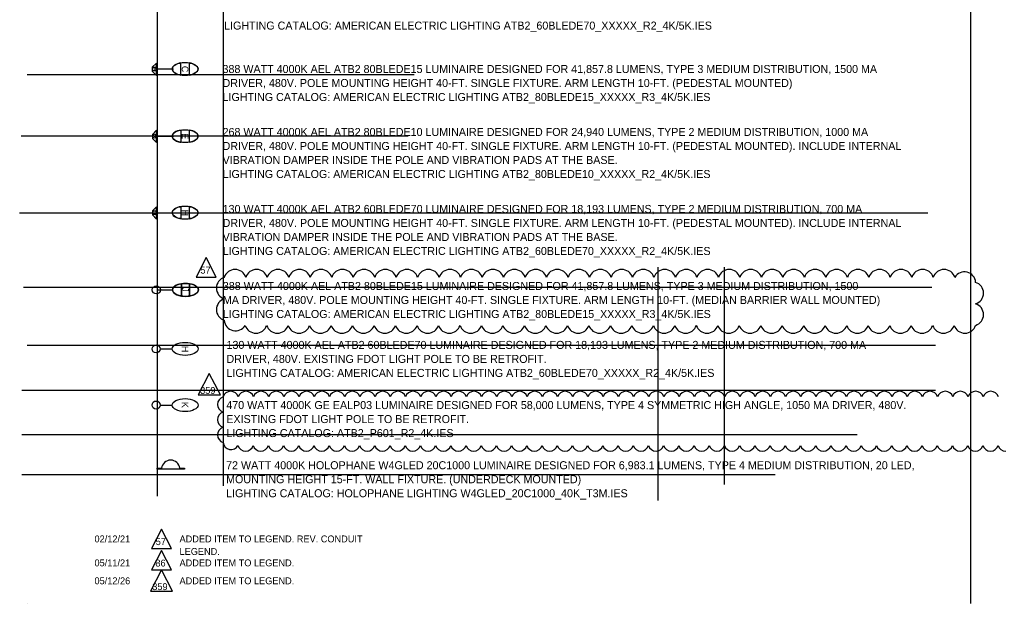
# Model space of a CAD drawing. Extents: x -0.7 to 15.2, y -0.9 to 9.6.
# Drawn here: x -0.62 to 7.94, y -0.9 to 4.21 of the extents above; entities that cross this region are included whole.
import ezdxf

# ---------------------------------------------------------------- set-up
doc = ezdxf.new("R2010")
doc.units = 0
for name, color, linetype in [('ActivePointCell_dp', 7, 'Continuous'), ('AdhocPoint_dp', 7, 'Continuous'), ('Cloud_dp', 7, 'Continuous'), ('LightingMisc', 7, 'Continuous'), ('Miscellaneous2', 7, 'Continuous'), ('PoleLight', 7, 'Continuous'), ('TextLabel', 7, 'Continuous'), ('TextMisc', 7, 'Continuous')]:
    doc.layers.add(name, color=color, linetype=linetype)

msp = doc.modelspace()

# ---------------------------------------------------------------- linework, layer by layer
at = {"layer": 'ActivePointCell_dp'}
for p, q in [((7.7, -0.9), (7.7, 9.6)), ((0.5844, 9.2534), (0.5844, 0.0367)), ((1.1641, 0.1282), (1.1641, 9.1337)), ((2.8316, 3.722), (-0.5519, 3.722)), ((2.7789, 3.1858), (-0.6046, 3.1858)), ((7.3238, 2.5135), (-0.6178, 2.5135)), ((4.9633, 2.0414), (4.9633, 0)), ((5.5423, 2.0414), (5.5423, 0.1403)), ((7.3568, 1.862), (-0.5847, 1.862)), ((7.39, 1.3545), (-0.5516, 1.3545)), ((7.39, 0.9614), (-0.599, 0.9614)), ((6.7052, 0.5747), (-0.599, 0.5747)), ((5.9878, 0.2247), (-0.599, 0.2247))]:
    msp.add_line(p, q, dxfattribs=at)
at = {"layer": 'AdhocPoint_dp'}
msp.add_line((-0.55, -0.9), (-0.55, -0.9), dxfattribs=at)
at = {"layer": 'Cloud_dp'}
for points in [[(1.0137, 2.1234), (0.9257, 1.9538), (1.1017, 1.9538)], [(1.0412, 1.1101), (0.9444, 0.9236), (1.138, 0.9236)], [(0.6228, -0.2504), (0.5348, -0.42), (0.7109, -0.42)], [(0.6228, -0.4378), (0.5348, -0.6074), (0.7109, -0.6074)], [(0.6228, -0.6056), (0.526, -0.7921), (0.7197, -0.7921)]]:
    msp.add_lwpolyline(points, close=True, dxfattribs=at)
for centre, radius, start, end in [((1.266, 1.9216), 0.0985, 17.5, 162.5), ((1.4538, 1.9216), 0.0985, 17.5, 162.5), ((1.6417, 1.9216), 0.0985, 17.5, 162.5), ((1.8295, 1.9216), 0.0985, 17.5, 162.5), ((2.0173, 1.9216), 0.0985, 17.5, 162.5), ((2.2051, 1.9216), 0.0985, 17.5, 162.5), ((2.393, 1.9216), 0.0985, 17.5, 162.5), ((2.5808, 1.9216), 0.0985, 17.5, 162.5), ((2.7686, 1.9216), 0.0985, 17.5, 162.5), ((2.9565, 1.9216), 0.0985, 17.5, 162.5), ((3.1443, 1.9216), 0.0985, 17.5, 162.5), ((3.3321, 1.9216), 0.0985, 17.5, 162.5), ((3.5199, 1.9216), 0.0985, 17.5, 162.5), ((3.7078, 1.9216), 0.0985, 17.5, 162.5), ((3.8956, 1.9216), 0.0985, 17.5, 162.5), ((4.0834, 1.9216), 0.0985, 17.5, 162.5), ((4.2713, 1.9216), 0.0985, 17.5, 162.5), ((4.4591, 1.9216), 0.0985, 17.5, 162.5), ((4.6469, 1.9216), 0.0985, 17.5, 162.5), ((4.8347, 1.9216), 0.0985, 17.5, 162.5), ((5.0226, 1.9216), 0.0985, 17.5, 162.5), ((5.2104, 1.9216), 0.0985, 17.5, 162.5), ((5.3982, 1.9216), 0.0985, 17.5, 162.5), ((5.5861, 1.9216), 0.0985, 17.5, 162.5), ((5.7739, 1.9216), 0.0985, 17.5, 162.5), ((5.9617, 1.9216), 0.0985, 17.5, 162.5), ((6.1495, 1.9216), 0.0985, 17.5, 162.5), ((6.3374, 1.9216), 0.0985, 17.5, 162.5), ((6.5252, 1.9216), 0.0985, 17.5, 162.5), ((6.713, 1.9216), 0.0985, 17.5, 162.5), ((6.9009, 1.9216), 0.0985, 17.5, 162.5), ((7.0887, 1.9216), 0.0985, 17.5, 162.5), ((7.2765, 1.9216), 0.0985, 17.5, 162.5), ((7.4643, 1.9216), 0.0985, 17.5, 162.5), ((7.6425, 1.9004), 0.0984, 3.94339, 148.94339), ((1.2017, 1.8573), 0.0985, 107.5, 252.5), ((7.7111, 1.8133), 0.0985, 287.5, 72.5), ((1.2017, 1.6695), 0.0985, 107.5, 252.5), ((7.7111, 1.6255), 0.0985, 287.5, 72.5), ((1.2702, 1.5823), 0.0984, 183.94339, 328.94339), ((1.4484, 1.5612), 0.0985, 197.5, 342.5), ((1.6363, 1.5612), 0.0985, 197.5, 342.5), ((1.8241, 1.5612), 0.0985, 197.5, 342.5), ((2.0119, 1.5612), 0.0985, 197.5, 342.5), ((2.1997, 1.5612), 0.0985, 197.5, 342.5), ((2.3876, 1.5612), 0.0985, 197.5, 342.5), ((2.5754, 1.5612), 0.0985, 197.5, 342.5), ((2.7632, 1.5612), 0.0985, 197.5, 342.5), ((2.9511, 1.5612), 0.0985, 197.5, 342.5), ((3.1389, 1.5612), 0.0985, 197.5, 342.5), ((3.3267, 1.5612), 0.0985, 197.5, 342.5), ((3.5145, 1.5612), 0.0985, 197.5, 342.5), ((3.7024, 1.5612), 0.0985, 197.5, 342.5), ((3.8902, 1.5612), 0.0985, 197.5, 342.5), ((4.078, 1.5612), 0.0985, 197.5, 342.5), ((4.2659, 1.5612), 0.0985, 197.5, 342.5), ((4.4537, 1.5612), 0.0985, 197.5, 342.5), ((4.6415, 1.5612), 0.0985, 197.5, 342.5), ((4.8293, 1.5612), 0.0985, 197.5, 342.5), ((5.0172, 1.5612), 0.0985, 197.5, 342.5), ((5.205, 1.5612), 0.0985, 197.5, 342.5), ((5.3928, 1.5612), 0.0985, 197.5, 342.5), ((5.5807, 1.5612), 0.0985, 197.5, 342.5), ((5.7685, 1.5612), 0.0985, 197.5, 342.5), ((5.9563, 1.5612), 0.0985, 197.5, 342.5), ((6.1441, 1.5612), 0.0985, 197.5, 342.5), ((6.332, 1.5612), 0.0985, 197.5, 342.5), ((6.5198, 1.5612), 0.0985, 197.5, 342.5), ((6.7076, 1.5612), 0.0985, 197.5, 342.5), ((6.8955, 1.5612), 0.0985, 197.5, 342.5), ((7.0833, 1.5612), 0.0985, 197.5, 342.5), ((7.2711, 1.5612), 0.0985, 197.5, 342.5), ((7.4589, 1.5612), 0.0985, 197.5, 342.5), ((7.6468, 1.5612), 0.0985, 197.5, 342.5), ((1.228, 0.885), 0.0697, 17.5, 162.5), ((1.3609, 0.885), 0.0697, 17.5, 162.5), ((1.4939, 0.885), 0.0697, 17.5, 162.5), ((1.6268, 0.885), 0.0697, 17.5, 162.5), ((1.7597, 0.885), 0.0697, 17.5, 162.5), ((1.8926, 0.885), 0.0697, 17.5, 162.5), ((2.0255, 0.885), 0.0697, 17.5, 162.5), ((2.1584, 0.885), 0.0697, 17.5, 162.5), ((2.2913, 0.885), 0.0697, 17.5, 162.5), ((2.4242, 0.885), 0.0697, 17.5, 162.5), ((2.5571, 0.885), 0.0697, 17.5, 162.5), ((2.69, 0.885), 0.0697, 17.5, 162.5), ((2.8229, 0.885), 0.0697, 17.5, 162.5), ((2.9559, 0.885), 0.0697, 17.5, 162.5), ((3.0888, 0.885), 0.0697, 17.5, 162.5), ((3.2217, 0.885), 0.0697, 17.5, 162.5), ((3.3546, 0.885), 0.0697, 17.5, 162.5), ((3.4875, 0.885), 0.0697, 17.5, 162.5), ((3.6204, 0.885), 0.0697, 17.5, 162.5), ((3.7533, 0.885), 0.0697, 17.5, 162.5), ((3.8862, 0.885), 0.0697, 17.5, 162.5), ((4.0191, 0.885), 0.0697, 17.5, 162.5), ((4.152, 0.885), 0.0697, 17.5, 162.5), ((4.2849, 0.885), 0.0697, 17.5, 162.5), ((4.4178, 0.885), 0.0697, 17.5, 162.5), ((4.5508, 0.885), 0.0697, 17.5, 162.5), ((4.6837, 0.885), 0.0697, 17.5, 162.5), ((4.8166, 0.885), 0.0697, 17.5, 162.5), ((4.9495, 0.885), 0.0697, 17.5, 162.5), ((5.0824, 0.885), 0.0697, 17.5, 162.5), ((5.2153, 0.885), 0.0697, 17.5, 162.5), ((5.3482, 0.885), 0.0697, 17.5, 162.5), ((5.4811, 0.885), 0.0697, 17.5, 162.5), ((5.614, 0.885), 0.0697, 17.5, 162.5), ((5.7469, 0.885), 0.0697, 17.5, 162.5), ((5.8798, 0.885), 0.0697, 17.5, 162.5), ((6.0128, 0.885), 0.0697, 17.5, 162.5), ((6.1457, 0.885), 0.0697, 17.5, 162.5), ((6.2786, 0.885), 0.0697, 17.5, 162.5), ((6.4115, 0.885), 0.0697, 17.5, 162.5), ((6.5444, 0.885), 0.0697, 17.5, 162.5), ((6.6773, 0.885), 0.0697, 17.5, 162.5), ((6.8102, 0.885), 0.0697, 17.5, 162.5), ((6.9431, 0.885), 0.0697, 17.5, 162.5), ((7.076, 0.885), 0.0697, 17.5, 162.5), ((7.2089, 0.885), 0.0697, 17.5, 162.5), ((7.3418, 0.885), 0.0697, 17.5, 162.5), ((7.4748, 0.885), 0.0697, 17.5, 162.5), ((7.6077, 0.885), 0.0697, 17.5, 162.5), ((7.7406, 0.885), 0.0697, 17.5, 162.5), ((7.8735, 0.885), 0.0697, 17.5, 162.5), ((1.1825, 0.8395), 0.0697, 107.5, 252.5), ((1.1825, 0.7066), 0.0697, 107.5, 252.5), ((1.1825, 0.5737), 0.0697, 107.5, 252.5), ((1.2308, 0.5145), 0.0696, 185.94047, 330.94047), ((1.3582, 0.5016), 0.0697, 197.5, 342.5), ((1.4911, 0.5016), 0.0697, 197.5, 342.5), ((1.624, 0.5016), 0.0697, 197.5, 342.5), ((1.7569, 0.5016), 0.0697, 197.5, 342.5), ((1.8898, 0.5016), 0.0697, 197.5, 342.5), ((2.0227, 0.5016), 0.0697, 197.5, 342.5), ((2.1556, 0.5016), 0.0697, 197.5, 342.5), ((2.2885, 0.5016), 0.0697, 197.5, 342.5), ((2.4214, 0.5016), 0.0697, 197.5, 342.5), ((2.5543, 0.5016), 0.0697, 197.5, 342.5), ((2.6873, 0.5016), 0.0697, 197.5, 342.5), ((2.8202, 0.5016), 0.0697, 197.5, 342.5), ((2.9531, 0.5016), 0.0697, 197.5, 342.5), ((3.086, 0.5016), 0.0697, 197.5, 342.5), ((3.2189, 0.5016), 0.0697, 197.5, 342.5), ((3.3518, 0.5016), 0.0697, 197.5, 342.5), ((3.4847, 0.5016), 0.0697, 197.5, 342.5), ((3.6176, 0.5016), 0.0697, 197.5, 342.5), ((3.7505, 0.5016), 0.0697, 197.5, 342.5), ((3.8834, 0.5016), 0.0697, 197.5, 342.5), ((4.0163, 0.5016), 0.0697, 197.5, 342.5), ((4.1493, 0.5016), 0.0697, 197.5, 342.5), ((4.2822, 0.5016), 0.0697, 197.5, 342.5), ((4.4151, 0.5016), 0.0697, 197.5, 342.5), ((4.548, 0.5016), 0.0697, 197.5, 342.5), ((4.6809, 0.5016), 0.0697, 197.5, 342.5), ((4.8138, 0.5016), 0.0697, 197.5, 342.5), ((4.9467, 0.5016), 0.0697, 197.5, 342.5), ((5.0796, 0.5016), 0.0697, 197.5, 342.5), ((5.2125, 0.5016), 0.0697, 197.5, 342.5), ((5.3454, 0.5016), 0.0697, 197.5, 342.5), ((5.4783, 0.5016), 0.0697, 197.5, 342.5), ((5.6112, 0.5016), 0.0697, 197.5, 342.5), ((5.7442, 0.5016), 0.0697, 197.5, 342.5), ((5.8771, 0.5016), 0.0697, 197.5, 342.5), ((6.01, 0.5016), 0.0697, 197.5, 342.5), ((6.1429, 0.5016), 0.0697, 197.5, 342.5), ((6.2758, 0.5016), 0.0697, 197.5, 342.5), ((6.4087, 0.5016), 0.0697, 197.5, 342.5), ((6.5416, 0.5016), 0.0697, 197.5, 342.5), ((6.6745, 0.5016), 0.0697, 197.5, 342.5), ((6.8074, 0.5016), 0.0697, 197.5, 342.5), ((6.9403, 0.5016), 0.0697, 197.5, 342.5), ((7.0732, 0.5016), 0.0697, 197.5, 342.5), ((7.2062, 0.5016), 0.0697, 197.5, 342.5), ((7.3391, 0.5016), 0.0697, 197.5, 342.5), ((7.472, 0.5016), 0.0697, 197.5, 342.5), ((7.6049, 0.5016), 0.0697, 197.5, 342.5), ((7.7378, 0.5016), 0.0697, 197.5, 342.5), ((7.8707, 0.5016), 0.0697, 197.5, 342.5), ((8.0036, 0.5016), 0.0697, 197.5, 342.5)]:
    msp.add_arc(centre, radius, start, end, dxfattribs=at)
at = {"layer": 'LightingMisc'}
for p, q in [((0.584, 0.2734), (0.5839, 0.2814)), ((0.5839, 0.2814), (0.6241, 0.2814)), ((0.8228, 0.2739), (0.584, 0.2734)), ((0.7826, 0.2818), (0.8228, 0.2819)), ((0.8228, 0.2819), (0.8228, 0.2739))]:
    msp.add_line(p, q, dxfattribs=at)
msp.add_arc((0.7034, 0.2737), 0.0796, 5.86956, 174.39115, dxfattribs=at)
at = {"layer": 'Miscellaneous2'}
msp.add_ellipse((0.8323, 1.8418), major_axis=(-0.1133, 0), ratio=0.5, start_param=4.391241, end_param=4.391271, dxfattribs=at)
at = {"layer": 'PoleLight'}
for p, q in [((0.5583, 3.7731), (0.7274, 3.7731)), ((0.7932, 3.7193), (0.7932, 3.8268)), ((0.8647, 3.8268), (0.8647, 3.7193)), ((0.5587, 3.1858), (0.7277, 3.1858)), ((0.7936, 3.132), (0.7936, 3.2395)), ((0.8651, 3.2395), (0.8651, 3.132)), ((0.7936, 2.463), (0.7936, 2.5705)), ((0.8651, 2.5705), (0.8651, 2.463)), ((0.5587, 2.5167), (0.7277, 2.5167)), ((0.7965, 1.7881), (0.7965, 1.8956)), ((0.7965, 1.8944), (0.7965, 1.7881)), ((0.868, 1.8956), (0.868, 1.7881)), ((0.868, 1.7881), (0.868, 1.8956)), ((0.5929, 1.8415), (0.7238, 1.8415)), ((0.6113, 1.3255), (0.7161, 1.3255)), ((0.6113, 0.8345), (0.7161, 0.8345))]:
    msp.add_line(p, q, dxfattribs=at)
for points in [[(0.5425, 3.789), (0.5426, 3.7532), (0.5783, 3.7175), (0.5782, 3.8248)], [(0.5429, 3.2017), (0.543, 3.1659), (0.5786, 3.1302), (0.5786, 3.2374)], [(0.5429, 2.5327), (0.543, 2.4969), (0.5786, 2.4612), (0.5786, 2.5684)]]:
    msp.add_lwpolyline(points, close=True, dxfattribs=at)
for centre, radius in [((0.5617, 3.7728), 0.0163), ((0.562, 3.1855), 0.0163), ((0.562, 2.5165), 0.0163), ((0.5779, 1.8415), 0.0354), ((0.5779, 1.8415), 0.0354), ((0.576, 1.3255), 0.0354), ((0.576, 0.8345), 0.0354)]:
    msp.add_circle(centre, radius, dxfattribs=at)
for centre in [(0.8289, 3.7731), (0.8293, 3.1858), (0.8293, 2.5167), (0.8323, 1.8418), (0.8293, 1.3255), (0.8293, 0.8345)]:
    msp.add_ellipse(centre, major_axis=(-0.1133, 0), ratio=0.5, dxfattribs=at)
for centre, start_param, end_param in [((0.8289, 3.7731), 5.033538, 6.283185), ((0.8289, 3.7731), 0, 0.847605), ((0.8289, 3.7731), 1.891945, 4.391241), ((0.8289, 3.7731), 0.847605, 1.249648), ((0.8293, 3.1858), 5.033538, 6.283185), ((0.8293, 3.1858), 0, 0.847605), ((0.8293, 3.1858), 1.891945, 4.391241), ((0.8293, 3.1858), 0.847605, 1.249648), ((0.8293, 2.5167), 5.033538, 6.283185), ((0.8293, 2.5167), 1.891945, 4.391241), ((0.8293, 2.5167), 0, 0.847605), ((0.8293, 2.5167), 0.847605, 1.249648), ((0.8323, 1.8418), 5.033538, 6.283185), ((0.8323, 1.8418), 4.391271, 5.033538), ((0.8323, 1.8418), 1.891945, 4.391241), ((0.8323, 1.8418), 0, 0.847605), ((0.8323, 1.8418), 0.847605, 1.249648), ((0.8323, 1.8418), 1.249648, 1.891946)]:
    msp.add_ellipse(centre, major_axis=(-0.1133, 0), ratio=0.5, start_param=start_param, end_param=end_param, dxfattribs=at)

# ---------------------------------------------------------------- texts
at = {"layer": 'Cloud_dp'}
for s, p in [('57', (0.963, 1.984)), ('359', (0.9607, 0.9323)), ('02/12/21', (0.0373, -0.3659)), ('57', (0.5721, -0.3898)), ('ADDED ITEM TO LEGEND. REV. CONDUIT ', (0.7806, -0.3659)), ('LEGEND.', (0.7806, -0.4759)), ('05/11/21', (0.0373, -0.5754)), ('86', (0.5695, -0.5772)), ('ADDED ITEM TO LEGEND.', (0.7806, -0.5754)), ('05/12/26', (0.0373, -0.7324)), ('ADDED ITEM TO LEGEND.', (0.7806, -0.7324)), ('359', (0.5423, -0.7834))]:
    msp.add_text(s, height=0.06, dxfattribs=at).set_placement(p)
at = {"layer": 'TextLabel'}
for s, rotation, p in [('C', 270.00003, (0.8003, 3.7999)), ('E', 270.00003, (0.8007, 3.2115)), ('H', 270.00003, (0.8007, 2.5429)), ('J', 270.00005, (0.8037, 1.8634)), ('H', 270.00003, (0.8007, 1.3517)), ('K', 270.00003, (0.8007, 0.8616))]:
    msp.add_text(s, height=0.0572, rotation=rotation, dxfattribs=at).set_placement(p)
at = {"layer": 'TextMisc'}
for s, p in [('LIGHTING CATALOG: AMERICAN ELECTRIC LIGHTING ATB2_60BLEDE70_XXXXX_R2_4K/5K.IES', (1.1699, 4.1176)), ('388 WATT 4000K AEL ATB2 80BLEDE15 LUMINAIRE DESIGNED FOR 41,857.8 LUMENS, TYPE 3 MEDIUM DISTRIBUTION, 1500 MA ', (1.1566, 3.7381)), ('DRIVER, 480V. POLE MOUNTING HEIGHT 40-FT. SINGLE FIXTURE. ARM LENGTH 10-FT. (PEDESTAL MOUNTED)', (1.1566, 3.6156)), ('LIGHTING CATALOG: AMERICAN ELECTRIC LIGHTING ATB2_80BLEDE15_XXXXX_R3_4K/5K.IES', (1.1566, 3.4931)), ('268 WATT 4000K AEL ATB2 80BLEDE10 LUMINAIRE DESIGNED FOR 24,940 LUMENS, TYPE 2 MEDIUM DISTRIBUTION, 1000 MA ', (1.157, 3.1875)), ('DRIVER, 480V. POLE MOUNTING HEIGHT 40-FT. SINGLE FIXTURE. ARM LENGTH 10-FT. (PEDESTAL MOUNTED). INCLUDE INTERNAL ', (1.157, 3.065)), ('VIBRATION DAMPER INSIDE THE POLE AND VIBRATION PADS AT THE BASE.', (1.157, 2.9425)), ('LIGHTING CATALOG: AMERICAN ELECTRIC LIGHTING ATB2_80BLEDE10_XXXXX_R2_4K/5K.IES', (1.157, 2.82)), ('130 WATT 4000K AEL ATB2 60BLEDE70 LUMINAIRE DESIGNED FOR 18,193 LUMENS, TYPE 2 MEDIUM DISTRIBUTION, 700 MA ', (1.1574, 2.5143)), ('DRIVER, 480V. POLE MOUNTING HEIGHT 40-FT. SINGLE FIXTURE. ARM LENGTH 10-FT. (PEDESTAL MOUNTED). INCLUDE INTERNAL ', (1.1574, 2.3918)), ('VIBRATION DAMPER INSIDE THE POLE AND VIBRATION PADS AT THE BASE.', (1.1574, 2.2693)), ('LIGHTING CATALOG: AMERICAN ELECTRIC LIGHTING ATB2_60BLEDE70_XXXXX_R2_4K/5K.IES', (1.1574, 2.1468)), ('388 WATT 4000K AEL ATB2 80BLEDE15 LUMINAIRE DESIGNED FOR 41,857.8 LUMENS, TYPE 3 MEDIUM DISTRIBUTION, 1500 ', (1.1594, 1.8408)), ('MA DRIVER, 480V. POLE MOUNTING HEIGHT 40-FT. SINGLE FIXTURE. ARM LENGTH 10-FT. (MEDIAN BARRIER WALL MOUNTED)', (1.1594, 1.7183)), ('LIGHTING CATALOG: AMERICAN ELECTRIC LIGHTING ATB2_80BLEDE15_XXXXX_R3_4K/5K.IES', (1.1594, 1.5958)), ('130 WATT 4000K AEL ATB2 60BLEDE70 LUMINAIRE DESIGNED FOR 18,193 LUMENS, TYPE 2 MEDIUM DISTRIBUTION, 700 MA ', (1.1912, 1.3255)), ('DRIVER, 480V. EXISTING FDOT LIGHT POLE TO BE RETROFIT.', (1.1912, 1.203)), ('LIGHTING CATALOG: AMERICAN ELECTRIC LIGHTING ATB2_60BLEDE70_XXXXX_R2_4K/5K.IES', (1.1912, 1.0805)), ('470 WATT 4000K GE EALP03 LUMINAIRE DESIGNED FOR 58,000 LUMENS, TYPE 4 SYMMETRIC HIGH ANGLE, 1050 MA DRIVER, 480V. ', (1.1895, 0.7995)), ('EXISTING FDOT LIGHT POLE TO BE RETROFIT.', (1.1895, 0.677)), ('LIGHTING CATALOG: ATB2_P601_R2_4K.IES', (1.1895, 0.5545)), ('72 WATT 4000K HOLOPHANE W4GLED 20C1000 LUMINAIRE DESIGNED FOR 6,983.1 LUMENS, TYPE 4 MEDIUM DISTRIBUTION, 20 LED, ', (1.1877, 0.2734)), ('MOUNTING HEIGHT 15-FT. WALL FIXTURE. (UNDERDECK MOUNTED)', (1.1877, 0.1509)), ('LIGHTING CATALOG: HOLOPHANE LIGHTING W4GLED_20C1000_40K_T3M.IES', (1.1877, 0.0284))]:
    msp.add_text(s, height=0.07, dxfattribs=at).set_placement(p)

doc.saveas('drawing.dxf')
